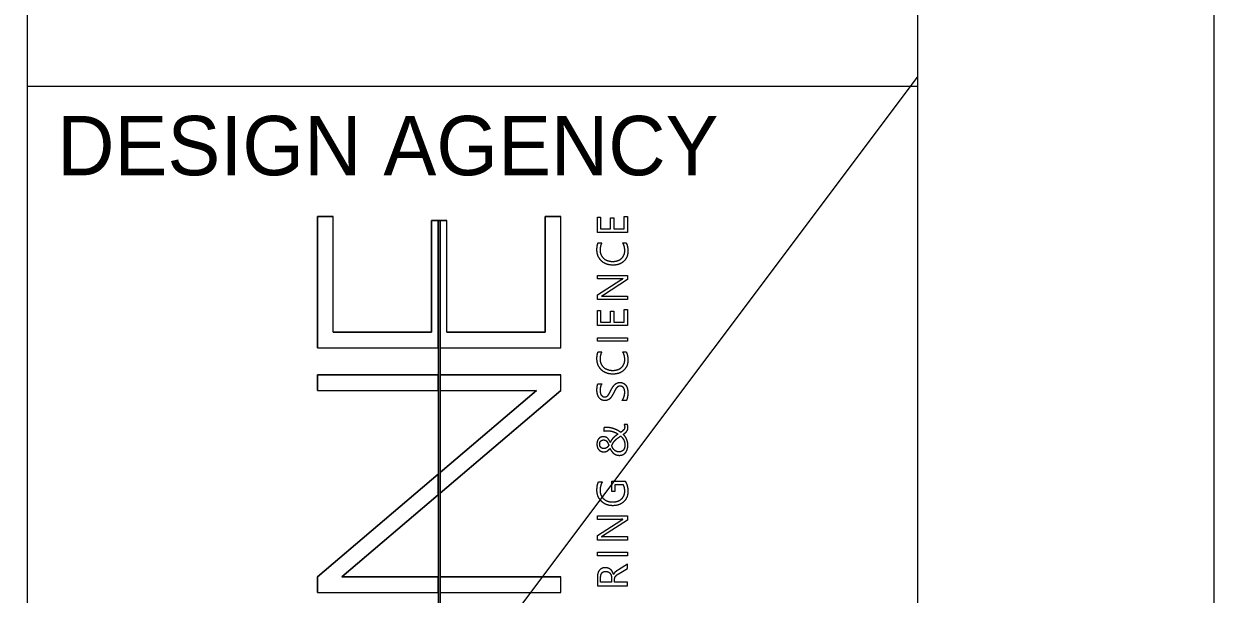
# Model space of a CAD drawing. Extents: x 0 to 88.1, y -6.1 to 35.8.
# Drawn here: x 31.994 to 34, y 4.144 to 5.105 of the extents above; entities that cross this region are included whole.
import ezdxf

# ---------------------------------------------------------------- set-up
doc = ezdxf.new("R2010")
doc.units = 0
for name, color, linetype in [('SC_Scratch1', 7, 'Continuous'), ('SH_Border', 7, 'Continuous'), ('SH_Cut_Line', 7, 'Continuous'), ('SH_Data', 7, 'Continuous')]:
    doc.layers.add(name, color=color, linetype=linetype)

msp = doc.modelspace()

# ---------------------------------------------------------------- linework, layer by layer
at = {"layer": 'SC_Scratch1'}
msp.add_line((32, 3.0154), (33.5, 5.0154), dxfattribs=at)
at = {"layer": 'SH_Border'}
for p, q in [((32, 0.5), (32, 21.5)), ((32, 5), (33.5, 5))]:
    msp.add_line(p, q, dxfattribs=at)
msp.add_lwpolyline([(1.5, 21.5), (33.5, 21.5), (33.5, 0.5), (1.5, 0.5)], close=True, dxfattribs=at)
at = {"layer": 'SH_Cut_Line'}
msp.add_lwpolyline([(0, 0), (34, 0), (34, 22), (0, 22)], close=True, dxfattribs=at)
at = {"layer": 'SH_Data'}
for p, q in [((32.489, 4.7806), (32.5153, 4.7806)), ((32.489, 4.5593), (32.489, 4.7806)), ((32.5153, 4.5856), (32.5153, 4.7806)), ((32.8724, 4.7806), (32.8988, 4.7806)), ((32.8724, 4.5856), (32.8724, 4.7806)), ((32.8988, 4.5593), (32.8988, 4.7806)), ((32.6807, 4.5856), (32.6807, 4.7735)), ((32.6807, 4.7735), (32.6923, 4.7735)), ((32.6923, 4.7735), (32.6923, 3.9885)), ((32.6923, 4.7735), (32.6923, 4.5593)), ((32.6923, 4.7735), (32.6954, 4.7735)), ((32.6954, 4.7735), (32.6954, 3.9885)), ((32.6954, 4.7735), (32.6954, 4.5593)), ((32.6954, 4.7735), (32.707, 4.7735)), ((32.707, 4.5856), (32.707, 4.7735)), ((32.9617, 4.7363), (32.968, 4.7363)), ((33.0032, 4.7363), (33.0089, 4.7363)), ((33.0035, 4.6756), (33.0035, 4.6758)), ((32.9676, 4.6464), (32.9676, 4.6462)), ((32.5153, 4.5856), (32.6807, 4.5856)), ((32.707, 4.5856), (32.8724, 4.5856)), ((32.489, 4.5593), (32.6923, 4.5593)), ((32.6954, 4.5593), (32.8988, 4.5593)), ((32.9617, 4.5527), (32.968, 4.5527)), ((33.0032, 4.5527), (33.0089, 4.5527)), ((32.489, 4.4872), (32.489, 4.5135)), ((32.489, 4.5135), (32.6923, 4.5135)), ((32.6923, 4.5135), (32.6923, 4.4872)), ((32.6954, 4.5135), (32.6954, 4.4872)), ((32.6954, 4.5135), (32.8988, 4.5135)), ((32.8988, 4.4872), (32.8988, 4.5135)), ((32.9615, 4.4988), (32.9681, 4.4988)), ((32.489, 4.4872), (32.6923, 4.4872)), ((32.6954, 4.3491), (32.8577, 4.4872)), ((32.8988, 4.4872), (32.6954, 4.3143)), ((32.6954, 4.4872), (32.8577, 4.4872)), ((33.009, 4.4703), (33.002, 4.4703)), ((32.9715, 4.4246), (32.9715, 4.419)), ((33.0109, 4.4302), (33.0055, 4.4302)), ((33.0118, 4.4248), (33.0118, 4.4248)), ((32.9709, 4.4041), (32.9709, 4.4041)), ((33.0068, 4.3953), (33.0068, 4.3953)), ((32.489, 4.1734), (32.6923, 4.3464)), ((32.6923, 4.3464), (32.6923, 4.3117)), ((32.6954, 4.3491), (32.6954, 4.3143)), ((32.9623, 4.3334), (32.9689, 4.3334)), ((32.6923, 4.3117), (32.5296, 4.1734)), ((33.0035, 4.2704), (33.0035, 4.2705)), ((32.9676, 4.2412), (32.9676, 4.241)), ((32.489, 4.147), (32.489, 4.1734)), ((32.5296, 4.1734), (32.6923, 4.1734)), ((32.6923, 4.1734), (32.6923, 4.147)), ((32.6954, 4.1734), (32.6954, 4.147)), ((32.6954, 4.1734), (32.8988, 4.1734)), ((32.8988, 4.147), (32.8988, 4.1734)), ((32.9877, 4.1776), (32.9876, 4.1776)), ((32.489, 4.147), (32.6923, 4.147)), ((32.6954, 4.147), (32.8988, 4.147))]:
    msp.add_line(p, q, dxfattribs=at)
for points in [[(32.489, 4.7806), (32.489, 4.5593), (32.6923, 4.5593), (32.6923, 4.7735), (32.6807, 4.7735), (32.6807, 4.5856), (32.5153, 4.5856), (32.5153, 4.7806)], [(32.707, 4.5856), (32.707, 4.7735), (32.6954, 4.7735), (32.6954, 4.5593), (32.8988, 4.5593), (32.8988, 4.7806), (32.8724, 4.7806), (32.8724, 4.5856)], [(33.011, 4.7806), (33.011, 4.7538), (32.9605, 4.7538), (32.9605, 4.7795), (32.9659, 4.7795), (32.9659, 4.7598), (32.9827, 4.7598), (32.9827, 4.778), (32.988, 4.778), (32.988, 4.7598), (33.0057, 4.7598), (33.0057, 4.7806)], [(33.011, 4.6236), (33.011, 4.5968), (32.9605, 4.5968), (32.9605, 4.6224), (32.9659, 4.6224), (32.9659, 4.6027), (32.9827, 4.6027), (32.9827, 4.6209), (32.988, 4.6209), (32.988, 4.6027), (33.0057, 4.6027), (33.0057, 4.6236)], [(33.011, 4.5762), (33.011, 4.5703), (32.9605, 4.5703), (32.9605, 4.5762)], [(32.489, 4.5135), (32.489, 4.4872), (32.6923, 4.4872), (32.6923, 4.5135)], [(32.6954, 4.5135), (32.6954, 4.4872), (32.8577, 4.4872), (32.6954, 4.3491), (32.6954, 4.3143), (32.8988, 4.4872), (32.8988, 4.5135)], [(32.489, 4.1734), (32.489, 4.147), (32.6923, 4.147), (32.6923, 4.1734), (32.5296, 4.1734), (32.6923, 4.3117), (32.6923, 4.3464)], [(33.011, 4.2148), (33.011, 4.2088), (32.9605, 4.2088), (32.9605, 4.2148)], [(32.6954, 4.1734), (32.6954, 4.147), (32.8988, 4.147), (32.8988, 4.1734)]]:
    msp.add_lwpolyline(points, close=True, dxfattribs=at)
for points in [[(32.8317, 3.984), (32.6986, 3.9511), (32.6986, 3.9885), (32.6954, 3.9885), (32.6954, 4.7735), (32.6923, 4.7735), (32.6923, 3.9885), (32.6891, 3.9885), (32.6891, 3.9487), (32.6149, 3.9303)], [(32.9961, 4.6754), (32.9605, 4.6754), (32.9605, 4.6813), (33.011, 4.6813), (33.011, 4.6741), (32.9708, 4.6481)], [(32.9745, 4.6465), (33.011, 4.6465), (33.011, 4.6406), (32.9605, 4.6406), (32.9605, 4.6483), (33.0001, 4.6736)], [(33.0042, 4.3285), (32.99, 4.3285), (32.99, 4.3174), (32.9847, 4.3174), (32.9847, 4.3344), (33.0076, 4.3344)], [(32.9961, 4.2702), (32.9605, 4.2702), (32.9605, 4.2761), (33.011, 4.2761), (33.011, 4.2688), (32.9708, 4.2428)], [(32.9745, 4.2413), (33.011, 4.2413), (33.011, 4.2354), (32.9605, 4.2354), (32.9605, 4.243), (33.0001, 4.2683)], [(32.9969, 4.1791), (33.011, 4.1875), (33.011, 4.1946), (32.9958, 4.1851)], [(32.9605, 4.1735), (32.9605, 4.1584), (33.011, 4.1584), (33.011, 4.1643), (32.9895, 4.1643), (32.9895, 4.1692)], [(32.9842, 4.1723), (32.9842, 4.1643), (32.9659, 4.1643), (32.9659, 4.1724)]]:
    msp.add_lwpolyline(points, dxfattribs=at)
for points in [[(32.9597, 4.7244), (32.9597, 4.7315), (32.9617, 4.7363)], [(32.968, 4.7363), (32.965, 4.7308), (32.965, 4.7243)], [(33.0066, 4.7231), (33.0066, 4.7307), (33.0032, 4.7363)], [(33.0089, 4.7363), (33.0119, 4.7307), (33.0119, 4.7223)], [(32.9671, 4.7059), (32.9597, 4.7132), (32.9597, 4.7244)], [(32.965, 4.7243), (32.965, 4.7156), (32.9708, 4.7102)], [(33.0011, 4.7098), (33.0066, 4.7149), (33.0066, 4.7231)], [(33.0119, 4.7223), (33.0119, 4.7115), (33.0049, 4.705)], [(32.9867, 4.6986), (32.9746, 4.6986), (32.9671, 4.7059)], [(32.9708, 4.7102), (32.9766, 4.7048), (32.9864, 4.7048)], [(32.9864, 4.7048), (32.9956, 4.7048), (33.0011, 4.7098)], [(33.0049, 4.705), (32.998, 4.6986), (32.9867, 4.6986)], [(33.0035, 4.6758), (33.0013, 4.6754), (32.9961, 4.6754)], [(33.0001, 4.6736), (33.0026, 4.6752), (33.0035, 4.6756)], [(32.9708, 4.6481), (32.9692, 4.6471), (32.9676, 4.6464)], [(32.9676, 4.6462), (32.9692, 4.6465), (32.9745, 4.6465)], [(32.9597, 4.5408), (32.9597, 4.548), (32.9617, 4.5527)], [(32.9671, 4.5223), (32.9597, 4.5296), (32.9597, 4.5408)], [(32.968, 4.5527), (32.965, 4.5473), (32.965, 4.5407)], [(32.965, 4.5407), (32.965, 4.532), (32.9708, 4.5266)], [(33.0011, 4.5262), (33.0066, 4.5313), (33.0066, 4.5395)], [(33.0066, 4.5395), (33.0066, 4.5471), (33.0032, 4.5527)], [(33.0119, 4.5387), (33.0119, 4.5279), (33.0049, 4.5215)], [(33.0089, 4.5527), (33.0119, 4.5471), (33.0119, 4.5387)], [(32.9867, 4.515), (32.9746, 4.515), (32.9671, 4.5223)], [(32.9708, 4.5266), (32.9766, 4.5212), (32.9864, 4.5212)], [(32.9864, 4.5212), (32.9956, 4.5212), (33.0011, 4.5262)], [(33.0049, 4.5215), (32.998, 4.515), (32.9867, 4.515)], [(32.9597, 4.4879), (32.9597, 4.4954), (32.9615, 4.4988)], [(32.9681, 4.4988), (32.965, 4.4943), (32.965, 4.4873)], [(32.986, 4.4927), (32.9875, 4.4951), (32.9893, 4.4969)], [(32.9893, 4.4969), (32.9911, 4.4988), (32.9933, 4.4998)], [(32.9933, 4.4998), (32.9955, 4.5009), (32.9983, 4.5009)], [(32.9987, 4.4947), (32.9967, 4.4947), (32.9951, 4.4938)], [(32.9983, 4.5009), (33.002, 4.5009), (33.0046, 4.4994)], [(33.0045, 4.492), (33.0025, 4.4947), (32.9987, 4.4947)], [(33.0046, 4.4994), (33.0072, 4.498), (33.0088, 4.4955)], [(33.0088, 4.4955), (33.0104, 4.493), (33.0112, 4.4898)], [(32.9605, 4.4815), (32.9597, 4.4846), (32.9597, 4.4879)], [(32.9629, 4.4759), (32.9613, 4.4783), (32.9605, 4.4815)], [(32.9671, 4.4719), (32.9646, 4.4734), (32.9629, 4.4759)], [(32.965, 4.4873), (32.965, 4.4854), (32.9654, 4.4834)], [(32.9654, 4.4834), (32.9658, 4.4815), (32.9667, 4.48)], [(32.9667, 4.48), (32.9677, 4.4785), (32.9691, 4.4775)], [(32.9691, 4.4775), (32.9705, 4.4766), (32.9726, 4.4766)], [(32.9726, 4.4766), (32.9746, 4.4766), (32.976, 4.4773)], [(32.976, 4.4773), (32.9774, 4.478), (32.9785, 4.4794)], [(32.9818, 4.474), (32.9802, 4.4723), (32.9781, 4.4713)], [(32.9785, 4.4794), (32.9797, 4.4808), (32.9808, 4.4828)], [(32.9808, 4.4828), (32.9819, 4.4849), (32.9832, 4.4875)], [(32.9849, 4.478), (32.9835, 4.4757), (32.9818, 4.474)], [(32.9832, 4.4875), (32.9845, 4.4902), (32.986, 4.4927)], [(32.9876, 4.4829), (32.9862, 4.4803), (32.9849, 4.478)], [(32.99, 4.4876), (32.9888, 4.4854), (32.9876, 4.4829)], [(32.9924, 4.4913), (32.9911, 4.4897), (32.99, 4.4876)], [(32.9951, 4.4938), (32.9936, 4.4929), (32.9924, 4.4913)], [(33.0039, 4.4732), (33.0048, 4.4748), (33.0053, 4.4767)], [(33.0066, 4.4839), (33.0066, 4.4893), (33.0045, 4.492)], [(33.0053, 4.4767), (33.0059, 4.4785), (33.0062, 4.4804)], [(33.0062, 4.4804), (33.0066, 4.4823), (33.0066, 4.4839)], [(33.0111, 4.4764), (33.0108, 4.4745), (33.0102, 4.4729)], [(33.0117, 4.48), (33.0115, 4.4782), (33.0111, 4.4764)], [(33.0112, 4.4898), (33.0119, 4.4865), (33.0119, 4.4829)], [(33.0119, 4.4829), (33.0119, 4.4817), (33.0117, 4.48)], [(32.9732, 4.4704), (32.9697, 4.4704), (32.9671, 4.4719)], [(32.9781, 4.4713), (32.976, 4.4704), (32.9732, 4.4704)], [(33.002, 4.4703), (33.0031, 4.4715), (33.0039, 4.4732)], [(33.0102, 4.4729), (33.0097, 4.4713), (33.009, 4.4703)], [(32.9737, 4.4249), (32.9727, 4.4249), (32.9715, 4.4246)], [(32.9715, 4.419), (32.9727, 4.4193), (32.9739, 4.4194)], [(32.9762, 4.4251), (32.9748, 4.425), (32.9737, 4.4249)], [(32.9739, 4.4194), (32.9751, 4.4196), (32.9764, 4.4196)], [(32.9827, 4.4244), (32.9794, 4.4251), (32.9762, 4.4251)], [(32.9764, 4.4196), (32.9816, 4.4196), (32.9864, 4.4182)], [(32.989, 4.4226), (32.9859, 4.4237), (32.9827, 4.4244)], [(32.9864, 4.4182), (32.9912, 4.4167), (32.9952, 4.4139)], [(32.9948, 4.42), (32.992, 4.4215), (32.989, 4.4226)], [(32.9952, 4.4139), (32.9931, 4.4125), (32.9912, 4.411)], [(32.9998, 4.4168), (32.9975, 4.4185), (32.9948, 4.42)], [(33.0027, 4.4191), (33.0015, 4.4181), (32.9998, 4.4168)], [(33.0048, 4.4211), (33.004, 4.4201), (33.0027, 4.4191)], [(33.004, 4.4134), (33.0059, 4.4147), (33.0073, 4.4159)], [(33.0061, 4.4233), (33.0057, 4.4222), (33.0048, 4.4211)], [(33.0055, 4.4302), (33.0059, 4.429), (33.0062, 4.428)], [(33.0065, 4.4258), (33.0065, 4.4244), (33.0061, 4.4233)], [(33.0062, 4.428), (33.0065, 4.4269), (33.0065, 4.4258)], [(33.0073, 4.4159), (33.0087, 4.4171), (33.0098, 4.4184)], [(33.0098, 4.4184), (33.0108, 4.4197), (33.0113, 4.4213)], [(33.0116, 4.4276), (33.0114, 4.4289), (33.0109, 4.4302)], [(33.0113, 4.4213), (33.0118, 4.4228), (33.0118, 4.4248)], [(33.0118, 4.4248), (33.0118, 4.4262), (33.0116, 4.4276)], [(32.9604, 4.4021), (32.9597, 4.3998), (32.9597, 4.3971)], [(32.9597, 4.3971), (32.9597, 4.3943), (32.9604, 4.3919)], [(32.9626, 4.406), (32.9612, 4.4044), (32.9604, 4.4021)], [(32.966, 4.4086), (32.964, 4.4077), (32.9626, 4.406)], [(32.9643, 4.3971), (32.9643, 4.3983), (32.9646, 4.3995)], [(32.9661, 4.3916), (32.9643, 4.3936), (32.9643, 4.3971)], [(32.9646, 4.3995), (32.965, 4.4007), (32.9658, 4.4018)], [(32.9658, 4.4018), (32.9666, 4.4028), (32.9679, 4.4034)], [(32.9704, 4.4095), (32.9679, 4.4095), (32.966, 4.4086)], [(32.9679, 4.4034), (32.9691, 4.4041), (32.9709, 4.4041)], [(32.9774, 4.4071), (32.9746, 4.4095), (32.9704, 4.4095)], [(32.9709, 4.4041), (32.974, 4.4041), (32.9761, 4.4019)], [(32.9761, 4.4019), (32.9781, 4.3997), (32.9797, 4.3953)], [(32.9822, 4.3998), (32.9802, 4.4047), (32.9774, 4.4071)], [(32.9797, 4.3953), (32.9791, 4.3941), (32.9782, 4.393)], [(32.9845, 4.4042), (32.9831, 4.4023), (32.9822, 4.3998)], [(32.9876, 4.4079), (32.9859, 4.4062), (32.9845, 4.4042)], [(32.9847, 4.3942), (32.9857, 4.3969), (32.987, 4.399)], [(32.9866, 4.3901), (32.9856, 4.392), (32.9847, 4.3942)], [(32.987, 4.399), (32.9882, 4.4011), (32.9899, 4.403)], [(32.9912, 4.411), (32.9893, 4.4096), (32.9876, 4.4079)], [(32.9899, 4.403), (32.9917, 4.4048), (32.994, 4.4067)], [(32.994, 4.4067), (32.9964, 4.4085), (32.9998, 4.4106)], [(32.9998, 4.4106), (33.0012, 4.4093), (33.0025, 4.4078)], [(33.0025, 4.4078), (33.0037, 4.4062), (33.0047, 4.4043)], [(33.007, 4.4101), (33.0055, 4.412), (33.004, 4.4134)], [(33.0047, 4.4043), (33.0057, 4.4024), (33.0063, 4.4002)], [(33.0068, 4.3953), (33.0068, 4.3929), (33.0062, 4.3908)], [(33.0063, 4.4002), (33.0068, 4.3979), (33.0068, 4.3953)], [(33.0095, 4.406), (33.0084, 4.4083), (33.007, 4.4101)], [(33.0112, 4.4011), (33.0105, 4.4037), (33.0095, 4.406)], [(33.0109, 4.3883), (33.0118, 4.3914), (33.0118, 4.3953)], [(33.0118, 4.3953), (33.0118, 4.3984), (33.0112, 4.4011)], [(32.9604, 4.3919), (32.9612, 4.3895), (32.9627, 4.3877)], [(32.9627, 4.3877), (32.9641, 4.386), (32.9663, 4.385)], [(32.9712, 4.3895), (32.968, 4.3895), (32.9661, 4.3916)], [(32.9663, 4.385), (32.9684, 4.384), (32.9712, 4.384)], [(32.9739, 4.3899), (32.9727, 4.3895), (32.9712, 4.3895)], [(32.9712, 4.384), (32.9731, 4.384), (32.9747, 4.3845)], [(32.9763, 4.3911), (32.9752, 4.3904), (32.9739, 4.3899)], [(32.9747, 4.3845), (32.9763, 4.385), (32.9776, 4.3858)], [(32.9782, 4.393), (32.9774, 4.3919), (32.9763, 4.3911)], [(32.9776, 4.3858), (32.979, 4.3867), (32.98, 4.3877)], [(32.98, 4.3877), (32.981, 4.3888), (32.9818, 4.3898)], [(32.9818, 4.3898), (32.9843, 4.3842), (32.9881, 4.3812)], [(32.9892, 4.3869), (32.9877, 4.3882), (32.9866, 4.3901)], [(32.9881, 4.3812), (32.9919, 4.3781), (32.9973, 4.3781)], [(32.9926, 4.3848), (32.9906, 4.3855), (32.9892, 4.3869)], [(32.9971, 4.384), (32.9945, 4.384), (32.9926, 4.3848)], [(33.0013, 4.3849), (32.9995, 4.384), (32.9971, 4.384)], [(32.9973, 4.3781), (33.0008, 4.3781), (33.0035, 4.3793)], [(33.0044, 4.3873), (33.0032, 4.3857), (33.0013, 4.3849)], [(33.0035, 4.3793), (33.0062, 4.3806), (33.0081, 4.3828)], [(33.0062, 4.3908), (33.0056, 4.3888), (33.0044, 4.3873)], [(33.0081, 4.3828), (33.0099, 4.3851), (33.0109, 4.3883)], [(33.0076, 4.3344), (33.0119, 4.3268), (33.0119, 4.3175)], [(32.9597, 4.3196), (32.9597, 4.3278), (32.9623, 4.3334)], [(32.9672, 4.3008), (32.9597, 4.3082), (32.9597, 4.3196)], [(32.9689, 4.3334), (32.965, 4.3273), (32.965, 4.3189)], [(32.965, 4.3189), (32.965, 4.3104), (32.9709, 4.305)], [(33.0011, 4.3046), (33.0066, 4.3096), (33.0066, 4.3183)], [(33.0066, 4.3183), (33.0066, 4.3242), (33.0042, 4.3285)], [(33.0119, 4.3175), (33.0119, 4.3067), (33.0049, 4.3)], [(32.9864, 4.2933), (32.9747, 4.2933), (32.9672, 4.3008)], [(32.9709, 4.305), (32.9767, 4.2995), (32.986, 4.2995)], [(32.986, 4.2995), (32.9956, 4.2995), (33.0011, 4.3046)], [(33.0049, 4.3), (32.9979, 4.2933), (32.9864, 4.2933)], [(33.0035, 4.2705), (33.0013, 4.2702), (32.9961, 4.2702)], [(33.0001, 4.2683), (33.0026, 4.2699), (33.0035, 4.2704)], [(32.9708, 4.2428), (32.9692, 4.2418), (32.9676, 4.2412)], [(32.9676, 4.241), (32.9692, 4.2413), (32.9745, 4.2413)], [(32.9613, 4.1796), (32.9605, 4.1768), (32.9605, 4.1735)], [(32.9638, 4.1844), (32.9622, 4.1824), (32.9613, 4.1796)], [(32.9681, 4.1877), (32.9655, 4.1865), (32.9638, 4.1844)], [(32.9659, 4.1724), (32.9659, 4.1774), (32.9681, 4.18)], [(32.974, 4.1888), (32.9706, 4.1888), (32.9681, 4.1877)], [(32.9681, 4.18), (32.9704, 4.1826), (32.9745, 4.1826)], [(32.9788, 4.188), (32.9766, 4.1888), (32.974, 4.1888)], [(32.9745, 4.1826), (32.9767, 4.1826), (32.9785, 4.1818)], [(32.9785, 4.1818), (32.9803, 4.1811), (32.9816, 4.1797)], [(32.9827, 4.1858), (32.981, 4.1872), (32.9788, 4.188)], [(32.9816, 4.1797), (32.9828, 4.1783), (32.9835, 4.1764)], [(32.9857, 4.1822), (32.9845, 4.1843), (32.9827, 4.1858)], [(32.9835, 4.1764), (32.9842, 4.1745), (32.9842, 4.1723)], [(32.9876, 4.1776), (32.9869, 4.1802), (32.9857, 4.1822)], [(32.989, 4.1798), (32.9883, 4.1789), (32.9877, 4.1776)], [(32.9907, 4.1816), (32.9897, 4.1807), (32.989, 4.1798)], [(32.9899, 4.1721), (32.9904, 4.1735), (32.9912, 4.1746)], [(32.9929, 4.1833), (32.9917, 4.1824), (32.9907, 4.1816)], [(32.9912, 4.1746), (32.9921, 4.1757), (32.9935, 4.1768)], [(32.9958, 4.1851), (32.9942, 4.1841), (32.9929, 4.1833)], [(32.9935, 4.1768), (32.9949, 4.1779), (32.9969, 4.1791)], [(32.9895, 4.1692), (32.9895, 4.1708), (32.9899, 4.1721)]]:
    msp.add_open_spline(points, degree=2, dxfattribs=at)

# ---------------------------------------------------------------- texts
msp.add_text('DESIGN AGENCY', height=0.1, dxfattribs=at).set_placement((32.05, 4.85))

doc.saveas('drawing.dxf')
